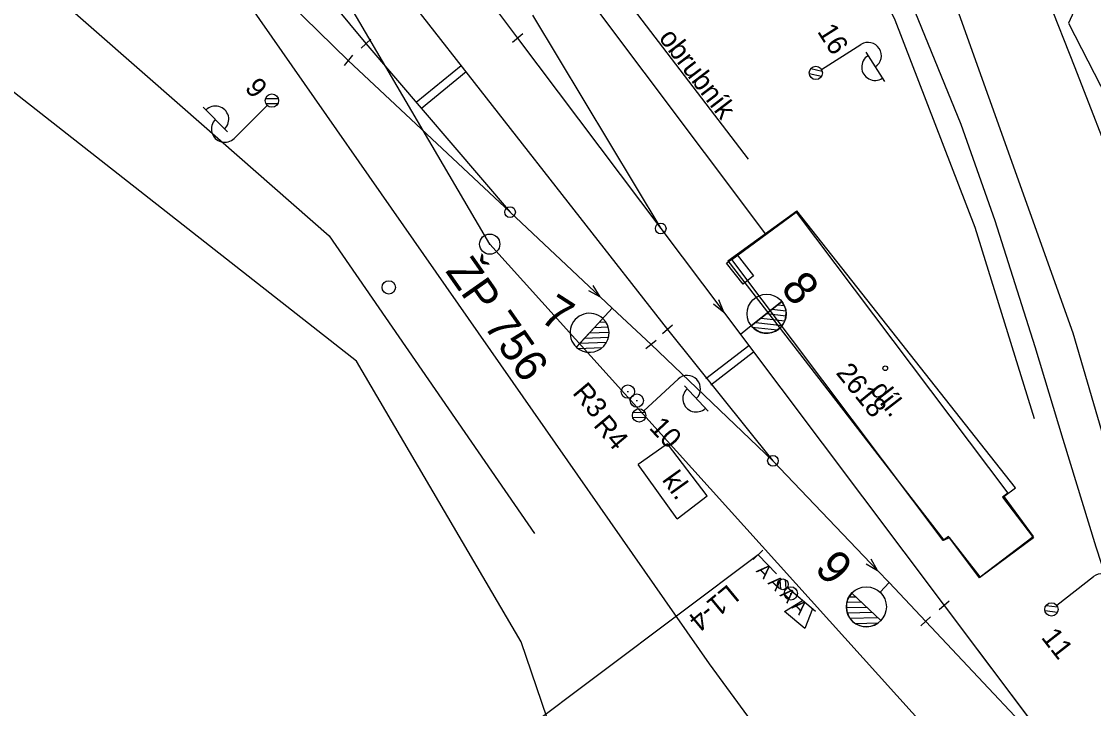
# Model space of a CAD drawing. Extents: x -804166 to -803706, y -1151030 to -1150147.
# Drawn here: x -803991 to -803910.7, y -1150447.5 to -1150395.9 of the extents above; entities that cross this region are included whole.
import ezdxf

# ---------------------------------------------------------------- set-up
doc = ezdxf.new("R2010")
doc.units = 0
for name, color, linetype in [('0381KM032-037P - Vrstva 1', 7, 'Continuous'), ('0381KM032-037P - Vrstva 2', 7, 'Continuous'), ('0381KM032-037P - Vrstva 23', 7, 'Continuous'), ('0381KM032-037P - Vrstva 25', 7, 'Continuous'), ('0381KM032-037P - Vrstva 27', 7, 'Continuous'), ('0381KM032-037P - Vrstva 33', 7, 'Continuous'), ('0381KM032-037P - Vrstva 36', 7, 'Continuous'), ('0381KM032-037P - Vrstva 4', 7, 'Continuous'), ('0381KM032-037P - Vrstva 49', 7, 'Continuous'), ('0381KM032-037P - Vrstva 51', 7, 'Continuous'), ('0381KM032-037P - Vrstva 55', 7, 'Continuous'), ('0381KM032-037P - Vrstva 57', 7, 'Continuous'), ('0381KM032-037P - Vrstva 59', 7, 'Continuous'), ('0381KM032-037P - Vrstva 6', 7, 'Continuous'), ('0381KM032-037P - Vrstva 7', 7, 'Continuous'), ('hran DP - hran DP', 7, 'Continuous'), ('vyt_sit - ohrožené', 7, 'Continuous'), ('vyt_sit - polygon', 7, 'Continuous')]:
    doc.layers.add(name, color=color, linetype=linetype)

msp = doc.modelspace()

# ---------------------------------------------------------------- linework, layer by layer
at = {"layer": '0381KM032-037P - Vrstva 1'}
msp.add_line((-803925.981, -1150438.008), (-803923.249, -1150440.918), dxfattribs=at)
for points in [[(-804090.387, -1150214.375), (-804086.648, -1150219.546), (-804073.823, -1150237.114), (-804072.555, -1150238.826), (-804064.047, -1150250.31), (-804062.807, -1150251.974), (-804052.288, -1150266.049), (-804042.5, -1150279.11), (-804026.546, -1150300.334), (-804011.272, -1150320.629), (-803993.373, -1150344.487), (-803965.171, -1150382.072), (-803953.841, -1150397.189)], [(-804093.97, -1150217.423), (-804088.165, -1150225.674), (-804077.507, -1150240.279), (-804068.519, -1150252.214), (-804067.312, -1150253.815), (-804055.014, -1150270.122), (-804046.09, -1150281.931), (-804030.046, -1150303.209), (-804014.756, -1150323.518), (-803996.92, -1150347.354), (-803968.884, -1150385.416), (-803942.597, -1150419.033)], [(-804095.554, -1150218.377), (-804090.738, -1150227.081), (-804084.011, -1150238.21), (-804078.761, -1150245.777), (-804072.115, -1150254.848), (-804070.853, -1150256.555), (-804059.975, -1150271.287), (-804049.56, -1150285.37), (-804034.127, -1150306.216), (-804018.794, -1150326.862), (-804001.176, -1150350.631), (-803980.37, -1150378.683), (-803972.82, -1150388.417), (-803965.206, -1150397.597)], [(-804011.14, -1150262.39), (-804005.45, -1150273.41), (-803998.73, -1150284.85), (-803991.51, -1150295.63), (-803978.8, -1150312.77), (-803963.69, -1150332.99), (-803952.21, -1150348.36), (-803946.3, -1150356.39), (-803941.6, -1150363.14), (-803936.71, -1150370.83), (-803932.05, -1150378.84), (-803927.78, -1150386.91), (-803924.06, -1150395.18), (-803920.62, -1150403.65), (-803918.06, -1150410.86), (-803915.07, -1150420.32), (-803912.96, -1150427.25), (-803910.49, -1150435.34), (-803907.334, -1150445.05), (-803903.668, -1150454.381), (-803897.938, -1150464.596), (-803891.973, -1150476.598)], [(-803962.118, -1150376.153), (-803948.983, -1150393.601), (-803935.254, -1150411.887)], [(-803974.334, -1150391.21), (-803966.535, -1150398.856)], [(-803975.617, -1150392.296), (-803939.473, -1150444.116), (-803928.265, -1150459.416), (-803914.534, -1150477.731)], [(-803952.72, -1150395.461), (-803943.112, -1150411.456), (-803938.373, -1150417.729), (-803937.129, -1150419.412)], [(-803953.841, -1150397.189), (-803943.112, -1150411.456), (-803938.373, -1150417.729), (-803937.129, -1150419.412)], [(-803965.206, -1150397.597), (-803954.41, -1150410.231), (-803947.654, -1150416.589), (-803946.748, -1150417.444)], [(-803966.535, -1150398.856), (-803954.41, -1150410.231), (-803947.654, -1150416.589), (-803946.748, -1150417.444)], [(-803946.748, -1150417.444), (-803943.834, -1150420.169)], [(-803942.597, -1150419.033), (-803934.696, -1150428.881), (-803926.85, -1150437.116), (-803925.981, -1150438.008)], [(-803937.129, -1150419.412), (-803921.855, -1150439.729)], [(-803943.834, -1150420.169), (-803934.696, -1150428.881), (-803926.85, -1150437.116), (-803925.981, -1150438.008)], [(-803921.855, -1150439.729), (-803911.864, -1150453.035), (-803902.83, -1150465.067), (-803901.897, -1150466.329)], [(-803923.249, -1150440.918), (-803911.864, -1150453.035), (-803902.83, -1150465.067), (-803901.897, -1150466.329)]]:
    msp.add_lwpolyline(points, dxfattribs=at)
at = {"layer": '0381KM032-037P - Vrstva 2'}
for p, q in [((-803952.72, -1150395.461), (-803943.112, -1150411.456)), ((-803964.834, -1150397.263), (-803965.578, -1150397.931)), ((-803953.461, -1150396.864), (-803954.221, -1150397.514)), ((-803965.206, -1150397.597), (-803954.41, -1150410.231)), ((-803966.224, -1150398.465), (-803966.846, -1150399.247)), ((-803949.432, -1150420.36), (-803946.748, -1150417.444)), ((-803936.326, -1150418.769), (-803934.035, -1150416.947)), ((-803934.035, -1150416.947), (-803936.325, -1150418.77)), ((-803934.332, -1150417.184), (-803933.858, -1150417.238)), ((-803949.441, -1150420.356), (-803947.452, -1150418.209)), ((-803935.578, -1150418.174), (-803933.814, -1150418.375)), ((-803935.162, -1150417.844), (-803933.728, -1150418.008)), ((-803934.748, -1150417.514), (-803933.739, -1150417.629)), ((-803947.044, -1150418.871), (-803948.102, -1150418.912)), ((-803947.214, -1150418.497), (-803947.737, -1150418.517)), ((-803942.22, -1150418.704), (-803942.974, -1150419.362)), ((-803942.597, -1150419.033), (-803934.696, -1150428.881)), ((-803936.326, -1150418.77), (-803937.129, -1150419.412)), ((-803936.325, -1150418.77), (-803936.326, -1150418.769)), ((-803936.249, -1150418.852), (-803934.363, -1150419.068)), ((-803935.993, -1150418.504), (-803934.008, -1150418.73)), ((-803947.027, -1150419.63), (-803948.833, -1150419.7)), ((-803946.986, -1150419.248), (-803948.468, -1150419.305)), ((-803943.447, -1150419.852), (-803944.221, -1150420.486)), ((-803949.44, -1150420.356), (-803949.441, -1150420.356)), ((-803947.516, -1150420.41), (-803949.285, -1150420.478)), ((-803947.184, -1150420.017), (-803949.198, -1150420.094)), ((-803925.981, -1150438.008), (-803926.667, -1150438.735)), ((-803928.995, -1150439.081), (-803928.501, -1150439.068)), ((-803926.606, -1150440.856), (-803928.788, -1150438.797)), ((-803928.788, -1150438.797), (-803926.606, -1150440.856)), ((-803929.192, -1150439.888), (-803927.678, -1150439.844)), ((-803929.154, -1150439.486), (-803928.09, -1150439.455)), ((-803921.481, -1150439.397), (-803922.229, -1150440.061)), ((-803921.855, -1150439.729), (-803911.864, -1150453.035)), ((-803929.121, -1150440.286), (-803927.266, -1150440.232)), ((-803928.926, -1150440.681), (-803926.856, -1150440.62)), ((-803922.888, -1150440.573), (-803923.61, -1150441.263)), ((-803928.533, -1150441.069), (-803926.793, -1150441.019))]:
    msp.add_line(p, q, dxfattribs=at)
for points in [[(-803953.841, -1150397.189), (-803943.112, -1150411.456), (-803938.373, -1150417.729), (-803937.129, -1150419.412)], [(-803966.535, -1150398.856), (-803954.41, -1150410.231), (-803947.654, -1150416.589), (-803946.748, -1150417.444)], [(-803948.535, -1150416.116), (-803947.654, -1150416.589), (-803948.18, -1150415.739)], [(-803939.162, -1150417.114), (-803938.373, -1150417.729), (-803938.749, -1150416.802)], [(-803943.834, -1150420.169), (-803934.696, -1150428.881), (-803926.85, -1150437.116), (-803925.981, -1150438.008)], [(-803927.709, -1150436.605), (-803926.85, -1150437.116), (-803927.339, -1150436.244)], [(-803923.249, -1150440.918), (-803911.864, -1150453.035), (-803901.897, -1150466.329)]]:
    msp.add_lwpolyline(points, dxfattribs=at)
for centre, radius in [((-803954.41, -1150410.231), 0.4), ((-803943.112, -1150411.456), 0.4), ((-803935.173, -1150417.854), 1.462), ((-803934.696, -1150428.881), 0.4), ((-803927.697, -1150439.826), 1.5)]:
    msp.add_circle(centre, radius, dxfattribs=at)
for centre, radius, start, end in [((-803935.18, -1150417.858), 1.464, 218.52891, 38.48976), ((-803948.446, -1150419.28), 1.462, 47.14037, 227.60989), ((-803948.445, -1150419.282), 1.464, 227.22989, 47.19074), ((-803927.697, -1150439.826), 1.5, 136.65549, 316.65549)]:
    msp.add_arc(centre, radius, start, end, dxfattribs=at)
at = {"layer": '0381KM032-037P - Vrstva 23'}
for p, q in [((-803938.071, -1150413.885), (-803932.913, -1150410.127)), ((-803916.52, -1150430.915), (-803932.913, -1150410.127)), ((-803938.071, -1150413.885), (-803921.901, -1150434.824)), ((-803942.605, -1150427.597), (-803944.792, -1150429.161)), ((-803939.631, -1150431.514), (-803942.605, -1150427.597)), ((-803941.885, -1150433.226), (-803944.792, -1150429.161)), ((-803917.389, -1150431.545), (-803916.52, -1150430.915)), ((-803941.885, -1150433.226), (-803939.631, -1150431.514)), ((-803939.631, -1150431.514), (-803939.631, -1150431.514)), ((-803917.389, -1150431.545), (-803915.2, -1150434.565)), ((-803921.901, -1150434.824), (-803921.458, -1150434.637)), ((-803919.171, -1150437.591), (-803921.458, -1150434.637)), ((-803919.171, -1150437.591), (-803915.2, -1150434.565)), ((-803919.171, -1150437.591), (-803919.171, -1150437.591))]:
    msp.add_line(p, q, dxfattribs=at)
at = {"layer": '0381KM032-037P - Vrstva 25'}
for p, q in [((-803931.062, -1150399.53), (-803928.104, -1150397.66)), ((-803927.73, -1150398.251), (-803926.341, -1150400.449)), ((-803931.864, -1150399.471), (-803931.006, -1150399.664)), ((-803931.982, -1150399.828), (-803931.048, -1150400.039)), ((-803971.78, -1150401.734), (-803972.737, -1150401.734)), ((-803971.817, -1150402.109), (-803972.696, -1150402.109)), ((-803975.581, -1150404.208), (-803977.42, -1150402.37)), ((-803972.612, -1150402.228), (-803975.086, -1150404.703)), ((-803944.371, -1150425.139), (-803941.814, -1150422.749)), ((-803941.336, -1150423.26), (-803939.56, -1150425.159)), ((-803945.169, -1150425.232), (-803944.29, -1150425.261)), ((-803945.218, -1150425.605), (-803944.262, -1150425.637)), ((-803913.427, -1150439.714), (-803910.666, -1150437.563)), ((-803914.23, -1150439.734), (-803913.357, -1150439.842)), ((-803914.313, -1150440.101), (-803913.362, -1150440.219))]:
    msp.add_line(p, q, dxfattribs=at)
msp.add_lwpolyline([(-803938.176, -1150414.066), (-803937.39, -1150413.447), (-803936.152, -1150415.018), (-803936.938, -1150415.637), (-803938.176, -1150414.066)], dxfattribs=at)
for centre in [(-803931.485, -1150399.797), (-803931.485, -1150399.797), (-803972.258, -1150401.874), (-803972.258, -1150401.874), (-803944.736, -1150425.481), (-803913.821, -1150440.021)]:
    msp.add_circle(centre, 0.5, dxfattribs=at)
for centre, start, end in [((-803927.57, -1150398.505), 302.29869, 122.29869), ((-803927.046, -1150399.357), 121.59611, 303.00126), ((-803976.492, -1150403.28), 314.30437, 135.70951), ((-803975.793, -1150403.996), 135.00694, 315.00694), ((-803941.131, -1150423.479), 313.08042, 133.08042), ((-803940.457, -1150424.218), 132.37785, 313.78299), ((-803910.051, -1150438.352), 307.9199, 127.9199)]:
    msp.add_arc(centre, 1, start, end, dxfattribs=at)
at = {"layer": '0381KM032-037P - Vrstva 27'}
for p, q in [((-803945.625, -1150423.694), (-803945.525, -1150423.694)), ((-803944.953, -1150424.366), (-803944.853, -1150424.366)), ((-803933.408, -1150438.822), (-803933.308, -1150438.822))]:
    msp.add_line(p, q, dxfattribs=at)
for centre in [(-803945.575, -1150423.694), (-803944.903, -1150424.366), (-803933.358, -1150438.822)]:
    msp.add_circle(centre, 0.5, dxfattribs=at)
at = {"layer": '0381KM032-037P - Vrstva 33'}
for p, q in [((-803934.191, -1150437.821), (-803934.134, -1150438.5)), ((-803933.793, -1150437.779), (-803933.735, -1150438.472)), ((-803931.499, -1150440.186), (-803933.637, -1150438.384)), ((-803933.842, -1150440.17), (-803932.492, -1150439.347)), ((-803932.314, -1150441.461), (-803933.842, -1150440.17)), ((-803931.728, -1150439.992), (-803932.314, -1150441.461))]:
    msp.add_line(p, q, dxfattribs=at)
msp.add_circle((-803933.957, -1150438.143), 0.401, dxfattribs=at)
msp.add_circle((-803933.957, -1150438.143), 0.401, dxfattribs=at)
at = {"layer": '0381KM032-037P - Vrstva 36'}
msp.add_circle((-803963.496, -1150415.874), 0.5, dxfattribs=at)
at = {"layer": '0381KM032-037P - Vrstva 4'}
msp.add_lwpolyline([(-804015.087, -1150257.699), (-804005.607, -1150276.645), (-803997.811, -1150289.613), (-803985.988, -1150305.967), (-803963.827, -1150335.545), (-803947.69, -1150357.387), (-803941.599, -1150366.016), (-803933.495, -1150379.543), (-803925.569, -1150395.827), (-803919.567, -1150411.363), (-803915.11, -1150425.701)], dxfattribs=at)
at = {"layer": '0381KM032-037P - Vrstva 49'}
for points in [[(-804010.873, -1150255.863), (-804001.608, -1150274.672), (-803994.699, -1150286.679), (-803981.461, -1150304.357), (-803936.046, -1150366.093), (-803921.768, -1150392.538), (-803912.222, -1150419.282), (-803908.812, -1150430.908)], [(-803920.94, -1150376.21), (-803910.018, -1150390.511), (-803912.553, -1150396.059), (-803903.866, -1150412.95), (-803903.684, -1150418.644), (-803901.421, -1150428.97), (-803900.537, -1150437.639), (-803895.89, -1150448.56), (-803892.01, -1150457.3), (-803887.412, -1150463.602), (-803875.883, -1150484.91), (-803874.859, -1150484.495), (-803872.322, -1150492.497), (-803872.997, -1150496.546), (-803874.041, -1150498.946)], [(-803995.514, -1150387.867), (-803978.951, -1150402.371), (-803967.974, -1150412.011), (-803952.572, -1150434.32)]]:
    msp.add_lwpolyline(points, dxfattribs=at)
at = {"layer": '0381KM032-037P - Vrstva 51'}
msp.add_line((-803947.116, -1150392.441), (-803936.561, -1150406.256), dxfattribs=at)
msp.add_lwpolyline([(-804015.087, -1150257.699), (-804005.607, -1150276.645), (-803997.811, -1150289.613), (-803985.988, -1150305.967), (-803963.827, -1150335.545), (-803947.69, -1150357.387), (-803941.599, -1150366.016), (-803933.495, -1150379.543), (-803925.569, -1150395.827), (-803919.567, -1150411.363), (-803915.11, -1150425.701)], dxfattribs=at)
at = {"layer": '0381KM032-037P - Vrstva 55'}
msp.add_lwpolyline([(-803937.77, -1150413.78), (-803932.96, -1150410.23), (-803917.09, -1150431.3), (-803917.49, -1150431.6), (-803915.17, -1150434.66), (-803919.22, -1150437.65), (-803921.53, -1150434.55), (-803921.93, -1150434.85)], close=True, dxfattribs=at)
at = {"layer": '0381KM032-037P - Vrstva 59'}
msp.add_circle((-803926.281, -1150421.943), 0.175, dxfattribs=at)
at = {"layer": '0381KM032-037P - Vrstva 6'}
for p, q in [((-803935.819, -1150435.933), (-803966.226, -1150458.779)), ((-803935.462, -1150435.582), (-803936.176, -1150436.284)), ((-803934.431, -1150437.345), (-803935.819, -1150435.933))]:
    msp.add_line(p, q, dxfattribs=at)
at = {"layer": '0381KM032-037P - Vrstva 7'}
for p, q in [((-803958.064, -1150399.253), (-803961.44, -1150402.011)), ((-803957.695, -1150399.725), (-803961.051, -1150402.467)), ((-803939.724, -1150422.708), (-803936.506, -1150420.241)), ((-803939.354, -1150423.181), (-803936.145, -1150420.721))]:
    msp.add_line(p, q, dxfattribs=at)
at = {"layer": 'hran DP - hran DP'}
for p, q in [((-803965.92, -1150421.41), (-804004.05, -1150391.51)), ((-803914.94, -1150392.05), (-803912.08, -1150399.4)), ((-803912.08, -1150399.4), (-803907, -1150412.45)), ((-803953.58, -1150442.45), (-803965.92, -1150421.41)), ((-803944.36, -1150469.51), (-803953.58, -1150442.45))]:
    msp.add_line(p, q, dxfattribs=at)
at = {"layer": 'vyt_sit - ohrožené'}
msp.add_line((-803955.981, -1150412.633), (-803955.881, -1150412.633), dxfattribs=at)
msp.add_circle((-803955.931, -1150412.633), 0.756, dxfattribs=at)
at = {"layer": 'vyt_sit - polygon'}
for p, q in [((-803955.931, -1150412.633), (-804016.513, -1150309.123)), ((-803872.981, -1150504.591), (-803955.931, -1150412.633))]:
    msp.add_line(p, q, dxfattribs=at)

# ---------------------------------------------------------------- texts
at = {"layer": '0381KM032-037P - Vrstva 2'}
for s, rotation, p in [('8', 308.50934, (-803934.183, -1150415.962)), ('7', 327.21032, (-803952.278, -1150418.346)), ('9', 311.65549, (-803931.656, -1150436.995))]:
    msp.add_text(s, height=2.5, rotation=rotation, dxfattribs=at).set_placement(p)
at = {"layer": '0381KM032-037P - Vrstva 23'}
for s, rotation, p in [('díl.', 307.67687, (-803927.463, -1150423.603)), ('kl.', 305.56966, (-803943.057, -1150430.309))]:
    msp.add_text(s, height=1.5, rotation=rotation, dxfattribs=at).set_placement(p)
at = {"layer": '0381KM032-037P - Vrstva 25'}
for s, rotation, p in [('16', 302.29869, (-803931.415, -1150396.684)), ('9', 310.00694, (-803974.353, -1150400.957)), ('10', 313.08042, (-803944.04, -1150426.443)), ('11', 307.9199, (-803914.644, -1150442.133))]:
    msp.add_text(s, height=1.5, rotation=rotation, dxfattribs=at).set_placement(p)
at = {"layer": '0381KM032-037P - Vrstva 27'}
for s, p in [('R3', (-803949.788, -1150423.809)), ('R4', (-803948.214, -1150426.236))]:
    msp.add_text(s, height=1.5, rotation=310, dxfattribs=at).set_placement(p)
at = {"layer": '0381KM032-037P - Vrstva 51'}
msp.add_text('obrubník', height=1.5, rotation=307.38072, dxfattribs=at).set_placement((-803943.316, -1150397.186))
at = {"layer": '0381KM032-037P - Vrstva 57'}
msp.add_text('2618', height=1.5, rotation=309.10252, dxfattribs=at).set_placement((-803930.031, -1150422.302))
at = {"layer": '0381KM032-037P - Vrstva 6'}
for s, height, rotation, p in [('  A A A A ', 1, 314.51818, (-803936.532, -1150436.634)), ('L1-4', 1.5, 219.51818, (-803938.057, -1150438.079))]:
    msp.add_text(s, height=height, rotation=rotation, dxfattribs=at).set_placement(p)
at = {"layer": 'vyt_sit - ohrožené'}
msp.add_text('ŽP 756', height=2.4, rotation=305, dxfattribs=at).set_placement((-803959.295, -1150414.657))

doc.saveas('drawing.dxf')
